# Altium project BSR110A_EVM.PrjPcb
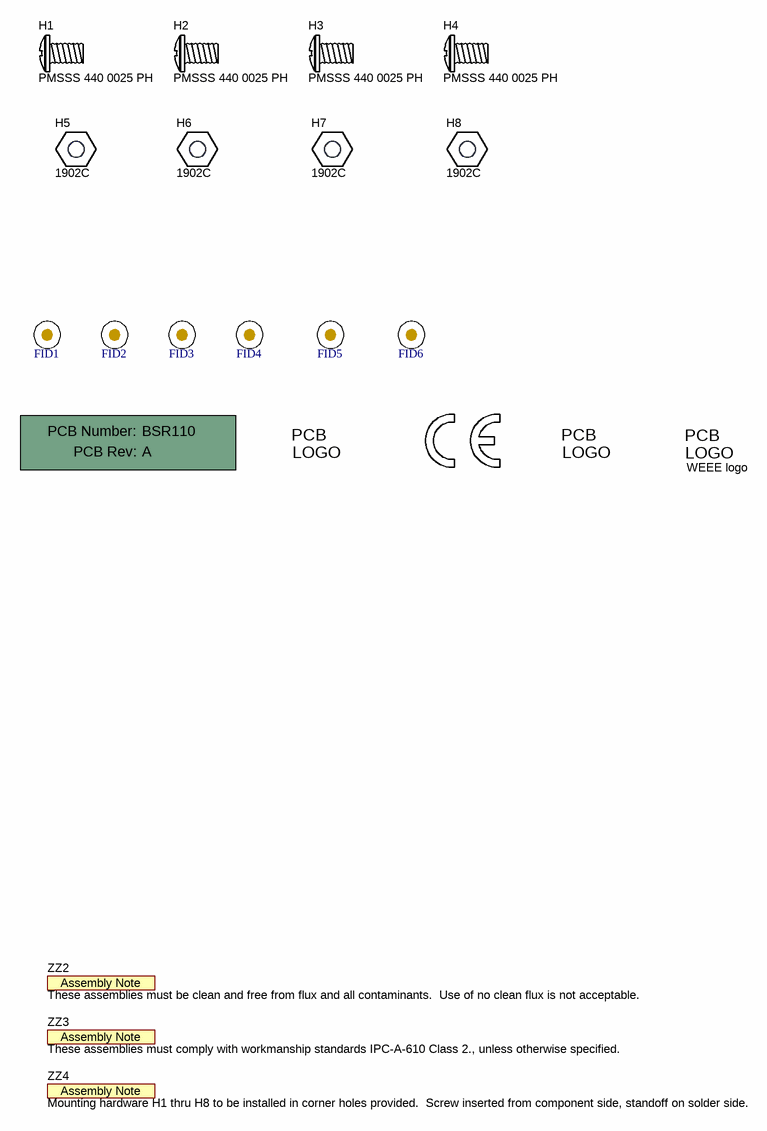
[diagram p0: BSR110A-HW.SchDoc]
CopyrightYear: 2018; PCB_Layout: K Nielson; PCB_Rev: A; PRJ_Customer: Public Release; PRJ_Engineer: T Hegarty; PRJ_Number: BSR110; PRJ_Title: LM25184 Flyback Converter; SCH_Rev: A; TechSupport: http://www.ti.com/support; TID: N/A
2 sheets, 57 parts. Net scope: global (net labels, ports and power ports of the same name join across sheets).
Board file: BSR110A.PcbDoc
Sheets:
  BSR110A-HW.SchDoc
  BSR110A-SCH.SchDoc

## Sheet BSR110A-HW.SchDoc: LM5180EVM-S03 Buck Converter Hardware
size 431 x 279 mm; Date: Not shown in title block; ApprovedBy: Not shown in title block; CheckedBy: Not shown in title block; Author: Not shown in title block; CompanyName: Not shown in title block; DrawnBy: K. Nielson; Engineer: Not shown in title block; Organization: Not shown in title block; Address1: Not shown in title block; Address2: Not shown in title block; Address3: Not shown in title block; Address4: Not shown in title block; DocumentNumber: 2; Revision: Use project parameter SCH_Rev; SheetNumber: 2; SheetTotal: 2; PageSetup: Record=PageOptions¦CenterHorizontal=True¦CenterVertical=True¦PrintScale=1.00¦XCorrection=1.00¦YCorrection=1.00¦PrintKind=0¦BorderSize=5000000¦LeftOffset=0¦BottomOffset=0¦Orientation=2¦PaperLength=1000¦PaperWidth=1000¦Scale=100¦PaperSource=15¦PrintQuality=600¦MediaType=1¦DitherType=10¦PaperKind=Letter¦PrintScaleMode=1

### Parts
!PCB  Printed Circuit Board  (value not drawn)  (mechanical)
FID1  Fiducial  [Fiducial10-20]  (value not drawn)
FID2  Fiducial  [Fiducial10-20]  (value not drawn)
FID3  Fiducial  [Fiducial10-20]  (value not drawn)
FID4  Fiducial  [Fiducial10-20]  (value not drawn)
FID5  Fiducial  [Fiducial10-20]  (value not drawn)
FID6  Fiducial  [Fiducial10-20]  (value not drawn)
H1  PMSSS 440 0025 PH  [B_F_PMSSS4400025PH]
H2  PMSSS 440 0025 PH  [B_F_PMSSS4400025PH]
H3  PMSSS 440 0025 PH  [B_F_PMSSS4400025PH]
H4  PMSSS 440 0025 PH  [B_F_PMSSS4400025PH]
H5  1902C  [Keystone_1902C]
H6  1902C  [Keystone_1902C]
H7  1902C  [Keystone_1902C]
H8  1902C  [Keystone_1902C]
Logo1  Texas Instruments  [TI_Stacked_Overlay_Small]  (value not drawn)  (no BOM)
Logo2  WEEE logo  [WEEE_Minimum]  (no BOM)
Logo3  FCC disclaimer  [FCC_disclaimer_stacked]  (value not drawn)  (no BOM)
LOGO4  CE Mark  [CE_Mark_5mm]  (value not drawn)  (no BOM)
ZZ2  These assemblies must be clean and free from flux and all contaminants.  Use of no clean flux is not acceptable.  [AssemblyNote]  (no BOM)
ZZ3  These assemblies must comply with workmanship standards IPC-A-610 Class 2., unless otherwise specified.  [AssemblyNote]  (no BOM)
ZZ4  Mounting hardware H1 thru H8 to be installed in corner holes provided.  Screw inserted from component side, standoff on solder side.  [AssemblyNote]  (no BOM)

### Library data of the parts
!PCB = CMP-0003618-2: Manufacturer: Any; PartNumber: BSR110
FID1-FID6 = CMP-0077181-1: Fiducial mark.  There is nothing to buy or mount.
H1 H2 H4 = CMP-0003715-1: MACHINE SCREW PAN PHILLIPS 4-40; Manufacturer: B&F Fastener Supply; CompType: Standoff; Component Classes: MountingHoles
H3 = CMP-0003715-1: MACHINE SCREW PAN PHILLIPS 4-40; Manufacturer: B&F Fastener Supply; CompType: Standoff; Component Classes: MountingHoles; Rule: PcbType=ProtelPcb
H5-H8 = CMP-0003610-1: Standoff, Hex, 0.5"L #4-40 Nylon; Manufacturer: Keystone; CompType: Hardware; Component Classes: MountingHoles
Logo1 = CMP-0074838-1: Texas Instrument Corporate Signature; SymbolCreator: a0412235; Lib Reference: TI_Logo
Logo2 = CMP-0074769-1
Logo3 = CMP-0074847-1: FCC_disclaimer
LOGO4 = CMP-0074844-1: SymbolCreator: a0412235
ZZ2-ZZ4 = AssemblyNote: SymbolCreator: codlsc

## Sheet BSR110A-SCH.SchDoc: LM5180EVM-S05 Buck Converter Schematic
size 431 x 279 mm; Date: Not shown in title block; ApprovedBy: Not shown in title block; CheckedBy: Not shown in title block; Author: Not shown in title block; CompanyName: Not shown in title block; DrawnBy: K Nielson; Engineer: Not shown in title block; Organization: Not shown in title block; Address1: Not shown in title block; Address2: Not shown in title block; Address3: Not shown in title block; Address4: Not shown in title block; DocumentNumber: 1; Revision: Use project parameter SCH_Rev; SheetNumber: 1; SheetTotal: 2; PageSetup: Record=PageOptions¦CenterHorizontal=True¦CenterVertical=True¦PrintScale=1.00¦XCorrection=1.00¦YCorrection=1.00¦PrintKind=0¦BorderSize=5000000¦LeftOffset=0¦BottomOffset=0¦Orientation=2¦PaperLength=1000¦PaperWidth=1000¦Scale=100¦PaperSource=15¦PrintQuality=600¦MediaType=1¦DitherType=10¦PaperKind=Letter¦PrintScaleMode=1
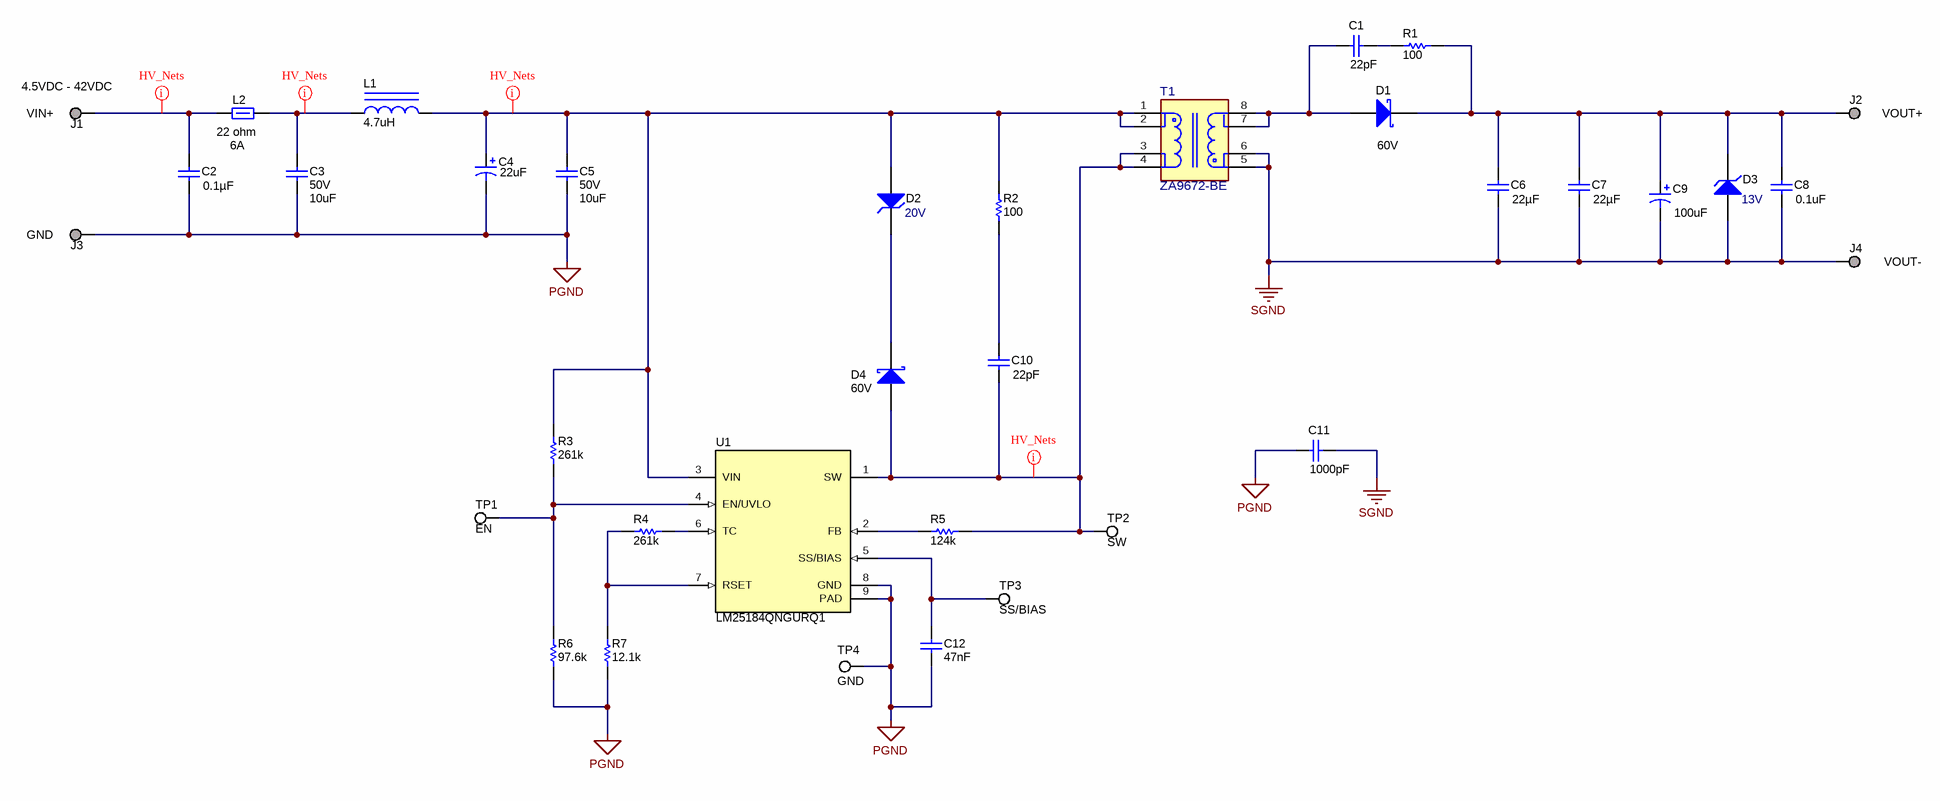
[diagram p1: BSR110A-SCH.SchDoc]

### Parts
C1  ValueDisplayed: 22pF  [0603_HV]  (hidden comment: GRM1885C2A220JA01D)
C2  ValueDisplayed: 0.1µF  [0603]  (hidden comment: C0603C104K5RACAUTO)
C3  VDC_V: 50V  ValueDisplayed: 10uF  [1210_280]  (hidden comment: CGA6P3X7S1H106K250AB)
C4  ValueDisplayed: 22uF  [Panasonic_D]  (hidden comment: EEH-ZC1H220P)
C5  VDC_V: 50V  ValueDisplayed: 10uF  [1210_280]  (hidden comment: CGA6P3X7S1H106K250AB)
C6  ValueDisplayed: 22µF  [1210_270]  (hidden comment: TMK325B7226KMHP)
C7  ValueDisplayed: 22µF  [1210_270]  (hidden comment: TMK325B7226KMHP)
C8  value 0.1uF  [0603L]  (hidden comment: C0603C104K5RACAUTO)
C9  ValueDisplayed: 100uF  [7343-31]  (hidden comment: T598D107M016ATE050)
C10  ValueDisplayed: 22pF  [0603_HV]  (hidden comment: GRM1885C2A220JA01D)
C11  ValueDisplayed: 1000pF  [1206_190]  (hidden comment: 202R18W102KV4E)
C12  Cap_F: 47nF  [0603L]  (hidden comment: GCM188R71E473KA37D)
D1  value 60V  [SOD-123HE]  (hidden comment: FSV360FP)
D2  value 20V  [SMA]  (hidden comment: 3SMAJ5932B-TP)
D3  value 13V  [SOD-523]  (hidden comment: BZT52C13T-7)
D4  value 60V  [SOD-123W]  (hidden comment: PMEG60T30ELRX)
J1  1573-2  [Keystone1573-2]  (value not drawn)
J2  1573-2  [Keystone1573-2]  (value not drawn)
J3  1573-2  [Keystone1573-2]  (value not drawn)
J4  1573-2  [Keystone1573-2]  (value not drawn)
L1  ValueDisplayed: 4.7uH  [XFL4030]  (hidden comment: XFL4030-472MEB)
L2  value 22 ohm  Value2: 6A  [0805_HV]  (hidden comment: 742792021)
R1  ValueDisplayed: 100  [0603L]  (hidden comment: CRCW0603100RFKEA)
R2  ValueDisplayed: 100  [0603L]  (hidden comment: CRCW0603100RFKEA)
R3  ValueDisplayed: 261k  [0603_HV]  (hidden comment: CRCW0603261KFKEA)
R4  ValueDisplayed: 261k  [0603L]  (hidden comment: CRCW0603261KFKEA)
R5  ValueDisplayed: 124k  [0603]  (hidden comment: CRCW0603124KFKEA)
R6  ValueDisplayed: 97.6k  [0603L]  (hidden comment: CRCW060397K6FKEA)
R7  ValueDisplayed: 12.1k  [0603L]  (hidden comment: CRCW060312K1FKEA)
T1  ZA9672-BE  [FP-ZA9672-BE_SMD8-MFG]
TP1  EN  [Testpoint_Keystone_Miniature]
TP2  SW  [Testpoint_Keystone_Miniature]
TP3  SS/BIAS  [Testpoint_Keystone_Miniature]
TP4  GND  [Testpoint_Keystone_Miniature]
U1  LM25184QNGURQ1  [NGU0008C]

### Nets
PGND: C2.2 C3.1 C4.2(-) C5.1 C11.2 C12.2 J3.1 R6.1 R7.1 TP4.1 U1.8(GND) U1.9(PAD)
SGND: C6.2 C7.2 C8.2 C9.2(-) C11.1 D3.2(A) J4.1 T1.5 T1.6
NetC1_1: C1.1 R1.2
NetC1_2: C1.2 D1.2(A) T1.7 T1.8
NetC2_1: C2.1 J1.1 L2.1
NetC3_2: C3.2 L1.1 L2.2
NetC4_1: C4.1(+) C5.2 D2.2(A) L1.2 R2.2 R3.2 T1.1 T1.2 U1.3(VIN)
NetC6_1: C6.1 C7.1 C8.1 C9.1(+) D1.1(K) D3.1(K) J2.1 R1.1
NetC10_1: C10.1 R2.1
NetC10_2: C10.2 D4.2(A) R5.2 T1.3 T1.4 TP2.1 U1.1(SW)
NetC12_1: C12.1 TP3.1 U1.5(SS/BIAS)
NetD2_1: D2.1(K) D4.1(K)
NetR3_1: R3.1 R6.2 TP1.1 U1.4(EN/UVLO)
NetR4_1: R4.1 R7.2 U1.7(RSET)
NetR4_2: R4.2 U1.6(TC)
NetR5_1: R5.1 U1.2(FB)

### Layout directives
net class HV_Nets: NetC2_1, NetC3_2, NetC4_1, NetC10_2

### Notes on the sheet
- (near J1) 4.5VDC - 42VDC
- (near J1) VIN+
- (near J2) VOUT+
- (near J3) GND
- (near J4) VOUT-

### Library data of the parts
C1 = CMP-0007255-4: CAP, CERM, 22 pF, 100 V, +/- 5%, C0G/NP0, 0603; Manufacturer: MuRata; TaMin_C: -55°C; Polarized: N; SizeAreaWB_mm2: 4.68; U/M: EA; Value: 22pF; TaMax_C: 125°C; SizeZ_mm: 1; SizeX_mm: 1.6; SizeY_mm: 0.8; Cap_Case: 0603; Value2: 100V; SizeArea_mm2: 1.28; CompType: Capacitor; AEC Category: Q200; Value1: Unknown
C2 = CMP-0079602-1: CAP, CERM, 0.1 µF, 50 V,+/- 10%, X7R, AEC-Q200 Grade 1, 0603; Manufacturer: Kemet; TaMin_C: -55°C; Polarized: N; SizeAreaWB_mm2: 4.68; U/M: EA; Value: 0.1uF; TaMax_C: 125°C; SizeZ_mm: 1; SizeX_mm: 1.6; SizeY_mm: 0.8; Value2: 50V; SizeArea_mm2: 1.28; AEC Qualified: Y; Cap_F: 100nF; AEC Category: Q200
C3 C5 = CMP-0009164-2: CAP, CERM, 10 uF, 50 V, +/- 10%, X7S, AEC-Q200 Grade 1, 1210; Manufacturer: TDK; TaMin_C: -55°C; Polarized: N; SizeAreaWB_mm2: 14.7; Value1: 0.002827 ohm; U/M: EA; Value: 10uF; TaMax_C: 125°C; SizeZ_mm: 2.8; SizeX_mm: 3.2; SizeY_mm: 2.5; SizeArea_mm2: 8; AEC Qualified: Y; Cap_F: 10µF; AEC Grade: 1; AEC Category: Q200; ESR_ohm: 2.827m; IRMS_A: 4.37286A
C4 = CMP-0012597-3: CAP, Polymer Hybrid, 22 uF, 50 V, +/- 20%, 0.08 ohm, AEC-Q200 Grade 1, D6.3xL5.8mm SMD; Manufacturer: Panasonic; TaMin_C: -55°C; ESR_ohm: 0.08; Polarized: Y; SizeAreaWB_mm2: 73.96; Value: 22uF; TaMax_C: 125°C; SizeZ_mm: 6.1; SizeX_mm: 6.6; Cap_Case: 6.3x5.8; Value2: 50V; SizeArea_mm2: 43.56; CompType: Capacitor; Cap_F: 22µF; IRMS_A: 750mA; AEC Grade: 1; AEC Category: Q200
C6 C7 = CMP-0080552-1: CAP, CERM, 22 µF, 25 V,+/- 10%, X7R, AEC-Q200 Grade 1, 1210; Manufacturer: Taiyo Yuden; TaMin_C: -55°C; Polarized: N; SizeAreaWB_mm2: 14.7; U/M: EA; Value: 22uF; TaMax_C: 125°C; SizeZ_mm: 2.7; SizeX_mm: 3.2; SizeY_mm: 2.5; Cap_Case: 1210; Value2: 25V; SizeArea_mm2: 8; AEC Qualified: Y; AEC Category: Q200; AEC Grade: 1
C8 = CMP-0079602-1: CAP, CERM, 0.1 µF, 50 V,+/- 10%, X7R, AEC-Q200 Grade 1, 0603; Manufacturer: Kemet; TaMin_C: -55°C; Polarized: N; SizeAreaWB_mm2: 4.68; U/M: EA; TaMax_C: 125°C; SizeZ_mm: 1; SizeX_mm: 1.6; SizeY_mm: 0.8; Cap_Case: 0603; Value2: 50V; SizeArea_mm2: 1.28; AEC Qualified: Y; Cap_F: 100nF; AEC Category: Q200; ValueDisplayed: 0.1µF
C9 = CMP-0012660-3: CAP, Tantalum Polymer, 100 uF, 16 V, +/- 20%, 0.05 ohm, AEC-Q200 Grade 1, 7343-31 SMD; Manufacturer: Kemet; TaMin_C: -55°C; ESR_ohm: 0.05; Polarized: Y; SizeAreaWB_mm2: 58.59; Value: 100uF; TaMax_C: 125°C; SizeZ_mm: 3.1; SizeX_mm: 7.3; SizeY_mm: 4.3; Value2: 16V; SizeArea_mm2: 31.39; CompType: Capacitor; Cap_F: 100µF; IRMS_A: 2.121A; AEC Grade: 1; AEC Category: Q200
C10 = CMP-0007255-4: CAP, CERM, 22 pF, 100 V, +/- 5%, C0G/NP0, 0603; Manufacturer: MuRata; TaMin_C: -55°C; Polarized: N; SizeAreaWB_mm2: 4.68; Value1: Unknown; U/M: EA; Value: 22pF; TaMax_C: 125°C; SizeZ_mm: 1; SizeX_mm: 1.6; SizeY_mm: 0.8; Cap_Case: 0603; Value2: 100V; SizeArea_mm2: 1.28; CompType: Capacitor; AEC Category: Q200
C11 = CMP-0008572-2: CAP, CERM, 1000 pF, 2000 V, +/- 10%, X7R, 1206_190; Manufacturer: Johanson Technology; TaMin_C: -55°C; Polarized: N; SizeAreaWB_mm2: 10.92; Value1: Unknown; U/M: EA; Value: 1000pF; TaMax_C: 125°C; SizeZ_mm: 1.9; SizeX_mm: 3.2; SizeY_mm: 1.6; Cap_Case: 1206; Value2: 2000V; SizeArea_mm2: 5.12; CompType: Capacitor; Cap_F: 1nF; VDC_V: 2kV; AEC Category: Q200
C12 = CMP-0007141-3: CAP, CERM, 0.047 uF, 25 V, +/- 10%, X7R, AEC-Q200 Grade 1, 0603; Manufacturer: MuRata; TaMin_C: -55°C; Polarized: N; SizeAreaWB_mm2: 4.68; Value1: Unknown; U/M: EA; TaMax_C: 125°C; SizeZ_mm: 1; SizeX_mm: 1.6; SizeY_mm: 0.8; Cap_Case: 0603; Value2: 25V; SizeArea_mm2: 1.28; AEC Qualified: Y; AEC Category: Q200
D1 = CMP-0028825-2: Diode, Schottky, 60 V, 3 A, AEC-Q101, SOD-123HE; Manufacturer: Fairchild Semiconductor; Value1: 3A; TJmax_C: 150°C; Green_REACh: Incomplete; SizeY_mm: 1.8; SizeZ_mm: 1; Vf_V: 650mV; SizeArea_mm2: 6.66; Green_Lifecycle: Not Set; SizeX_mm: 3.7; Value2: 0.65V; SizeAreaWB_mm2: 13.16; AEC Category: Q101; AEC Qualified: Y
D2 = CMP-0005511-4: Diode, Zener, 20 V, 3 W, SMA; Manufacturer: Micro Commercial Components; SizeArea_mm2: 16.3228; Power_W: 3W; SizeAreaWB_mm2: 37.3428; SizeY_mm: 2.92; AEC Category: Q101; RJA_CperW: 226; SizeZ_mm: 2.87; SizeX_mm: 5.59
D3 = CMP-0005879-5: Diode, Zener, 13 V, 300 mW, SOD-523; Manufacturer: Diodes Inc.; Power_W: 300mW; SizeAreaWB_mm2: 5.13; Value1: 0.3W; RJA_CperW: 417; SizeZ_mm: 0.65; SizeX_mm: 1.7; SizeY_mm: 0.9; SizeArea_mm2: 1.53; AEC Category: Q101
D4 = CMP-0085903-1: Diode, Schottky, 60 V, 3 A, AEC-Q101, SOD-123W; Manufacturer: Nexperia; Io_A: 3A; SizeAreaWB_mm2: 12.15; TJmax_C: 175°C; SizeZ_mm: 1; SizeX_mm: 3.5; SizeY_mm: 1.7; Vf_V: 620mV; Value2: 0.62V; SizeArea_mm2: 5.95; AEC Qualified: Y; AEC Category: Q101
J1-J4 = CMP-0055119-1: Terminal, Turret, TH, Double; Manufacturer: Keystone; CT: FALSE; Green_REACh: Passed; CompType: Turret Terminal; Green_Lifecycle: Active
L1 = CMP-0061153-1: Inductor, Shielded, Composite, 4.7 uH, 2.1 A, 0.03 ohm, SMD; Manufacturer: Coilcraft; Isat: 2.1A @ 30% inductance drop; Irms: 7.5A @ 40C rise; Green_Lifecycle: Not Set; SizeAreaWB_mm2: 25; DCR_ohm: 0.03; Green_REACh: Incomplete; Value: 4.7uH; Imax_A: 2.1A; SizeZ_mm: 3.1; SizeX_mm: 4; SizeArea_mm2: 16; Ind_H: 4.7µH; AEC Qualified: N; AEC Category: Q200
L2 = CMP-0003072-1: Ferrite Bead, 22 ohm @ 100 MHz, 6 A, 0805; Manufacturer: Wurth Elektronik; Ztyp@1GHz_Ohm: 40.219; ZTyp@100MHz_Ohm: 22; SizeAreaWB_mm2: 6.75; DCR_ohm: 8m; Value1: 0.008 ohm; SizeZ_mm: 1.45; SizeX_mm: 2; SizeY_mm: 1.25; SizeArea_mm2: 2.5
R1 R2 = CMP-0021991-4: RES, 100, 1%, 0.1 W, AEC-Q200 Grade 0, 0603; Manufacturer: Vishay-Dale; Power_W: 100mW; TempCo: 100 ppm/C; Value_Code: 100R; Value: 100; EIA_Code: E96; SizeX_mm: 1.6; SizeY_mm: 0.8; SizeZ_mm: 1; Value2: 0.1W; SizeArea_mm2: 1.28; AEC Qualified: Y; VDC_V: 75V; AEC Category: Q200; AEC Grade: 0
R3 R4 = CMP-0022244-4: RES, 261 k, 1%, 0.1 W, AEC-Q200 Grade 0, 0603; Manufacturer: Vishay-Dale; Power_W: 100mW; TempCo: 100 ppm/C; Value: 261k; EIA_Code: E96; SizeX_mm: 1.6; SizeY_mm: 0.8; SizeZ_mm: 1; Value2: 0.1W; SizeArea_mm2: 1.28; AEC Qualified: Y; VDC_V: 75V; AEC Category: Q200; AEC Grade: 0
R5 = CMP-0022026-4: RES, 124 k, 1%, 0.1 W, AEC-Q200 Grade 0, 0603; Manufacturer: Vishay-Dale; Power_W: 100mW; TempCo: 100 ppm/C; Value: 124k; EIA_Code: E96; SizeX_mm: 1.6; SizeY_mm: 0.8; SizeZ_mm: 1; Value2: 0.1W; SizeArea_mm2: 1.28; AEC Qualified: Y; VDC_V: 75V; AEC Category: Q200; AEC Grade: 0
R6 = CMP-0022663-4: RES, 97.6 k, 1%, 0.1 W, AEC-Q200 Grade 0, 0603; Manufacturer: Vishay-Dale; Power_W: 100mW; TempCo: 100 ppm/C; Value_Code: 97k6; Value: 97.6k; EIA_Code: E96; SizeX_mm: 1.6; SizeY_mm: 0.8; SizeZ_mm: 1; Value2: 0.1W; SizeArea_mm2: 1.28; AEC Qualified: Y; VDC_V: 75V; AEC Category: Q200; AEC Grade: 0
R7 = CMP-0022030-4: RES, 12.1 k, 1%, 0.1 W, AEC-Q200 Grade 0, 0603; Manufacturer: Vishay-Dale; Power_W: 100mW; TempCo: 100 ppm/C; Value_Code: 12k1; Value: 12.1k; EIA_Code: E96; SizeX_mm: 1.6; SizeY_mm: 0.8; SizeZ_mm: 1; Value2: 0.1W; SizeArea_mm2: 1.28; AEC Qualified: Y; VDC_V: 75V; AEC Category: Q200; AEC Grade: 0
T1 = CMP-0088070-1: FLYBACK TRANSFORMER; Manufacturer: Coilcraft; DCR_ohm: 0.035; Ind_H: 6.3µH; Ns1toNp: 1:1; SizeZ_mm: 10mm; AEC Qualified: No
TP1-TP4 = CMP-0055152-1: Test Point, Miniature, SMT; Manufacturer: Keystone; PartNumber: 5015; CNHeader: FALSE; Green_Lifecycle: Active; Green_REACh: Passed; CT: TRUE
U1 = CMP-0860959-2: 42-VIN PSR Flyback DC/DC Converter with 65-V, 4-A Integrated MOSFET, NGU0008C (WSON-8); Manufacturer: Texas Instruments; SizeArea_mm2: 16; SizeY_mm: 4; SizeAreaWB_mm2: 25; CompType: IC; AEC Category: Q200; SizeZ_mm: 0.8; AEC Qualified: Y

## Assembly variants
001: not fitted FID1 FID2 FID3 FID4 FID5 FID6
